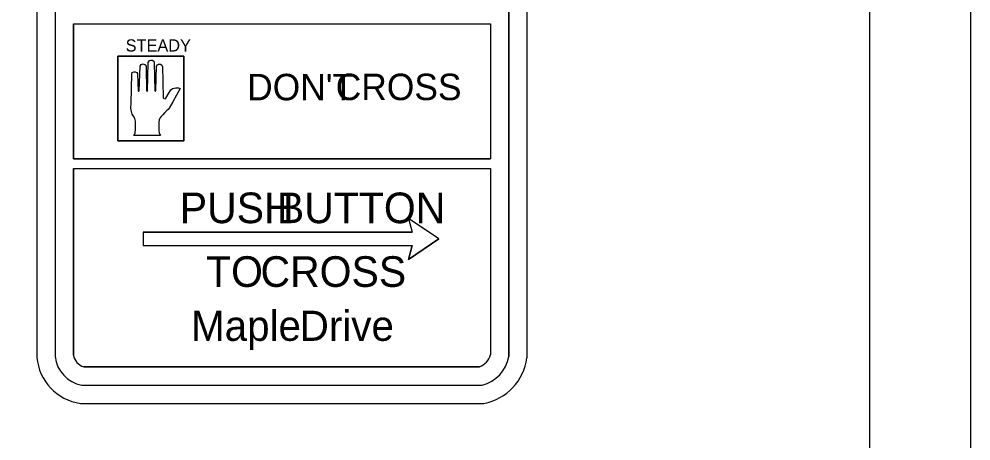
# Model space of a CAD drawing. Extents: x 1896459 to 1901611, y 1616229 to 1617416.
# Drawn here: x 1897924.9 to 1898159.1, y 1616865.6 to 1616969.5 of the extents above; entities that cross this region are included whole.
import ezdxf

# ---------------------------------------------------------------- set-up
doc = ezdxf.new("R2010")
doc.units = 0
for name, color, linetype in [('ROW_PR_Notes', 7, 'Continuous'), ('Sheets_General Details', 7, 'Continuous'), ('Signals_EX_Above Ground', 7, 'Continuous')]:
    doc.layers.add(name, color=color, linetype=linetype)

msp = doc.modelspace()

# ---------------------------------------------------------------- linework, layer by layer
at = {"layer": 'ROW_PR_Notes'}
for p, q in [((1897929.26, 1617065.93), (1897929.26, 1616886.19)), ((1897933.76, 1617065.54), (1897933.76, 1616886.41)), ((1897933.76, 1617065.54), (1897933.76, 1616886.41)), ((1898045.34, 1617065.54), (1898045.34, 1616886.41)), ((1898045.34, 1616886.41), (1898045.34, 1617065.54)), ((1898049.84, 1617065.89), (1898049.84, 1616886.08)), ((1897938.26, 1616968.32), (1898040.84, 1616968.32)), ((1897938.26, 1616968.32), (1897938.26, 1616935.04)), ((1897938.26, 1616968.32), (1898040.84, 1616968.32)), ((1897938.26, 1616935.04), (1897938.26, 1616968.32)), ((1898040.84, 1616968.32), (1898040.84, 1616935.04)), ((1898040.84, 1616968.32), (1898040.84, 1616935.04)), ((1897959.71, 1616940.81), (1897959.72, 1616940.82)), ((1897959.72, 1616940.82), (1897959.71, 1616940.81)), ((1897938.26, 1616935.04), (1898040.84, 1616935.04)), ((1898040.84, 1616935.04), (1897938.26, 1616935.04)), ((1897938.26, 1616932.71), (1898040.84, 1616932.71)), ((1897938.26, 1616932.71), (1897938.26, 1616886.7)), ((1897938.26, 1616886.7), (1897938.26, 1616932.71)), ((1897938.26, 1616932.71), (1898040.84, 1616932.71)), ((1898040.84, 1616932.71), (1898040.84, 1616886.85)), ((1898040.84, 1616932.71), (1898040.84, 1616886.85)), ((1898028.16, 1616915.34), (1898020.68, 1616920.42)), ((1898020.68, 1616920.42), (1898021.56, 1616916.98)), ((1898028.16, 1616915.34), (1898020.68, 1616920.42)), ((1898020.68, 1616920.42), (1898021.56, 1616916.98)), ((1897955.43, 1616916.98), (1897955.43, 1616913.71)), ((1897955.43, 1616916.98), (1898021.56, 1616916.98)), ((1898021.56, 1616916.98), (1897955.43, 1616916.98)), ((1897955.43, 1616916.98), (1897955.43, 1616913.71)), ((1898028.16, 1616915.34), (1898020.68, 1616910.27)), ((1898020.68, 1616910.27), (1898028.16, 1616915.34)), ((1897955.43, 1616913.71), (1898021.56, 1616913.71)), ((1897955.43, 1616913.71), (1898021.56, 1616913.71)), ((1898020.68, 1616910.27), (1898021.56, 1616913.71)), ((1898021.56, 1616913.71), (1898020.68, 1616910.27)), ((1897940.8, 1616883.88), (1898038.16, 1616883.88)), ((1898038.16, 1616883.88), (1897940.8, 1616883.88)), ((1897940.32, 1616879.38), (1898038.79, 1616879.38)), ((1897940.32, 1616879.38), (1898038.79, 1616879.38)), ((1897939.96, 1616874.88), (1898039.26, 1616874.88))]:
    msp.add_line(p, q, dxfattribs=at)
msp.add_lwpolyline([(1897949.15, 1616960.33), (1897965.4, 1616960.33), (1897965.4, 1616939.49), (1897949.15, 1616939.49)], close=True, dxfattribs=at)
for points in [[(1897949.15, 1616939.49), (1897965.4, 1616939.49), (1897965.4, 1616960.33), (1897949.15, 1616960.33), (1897949.15, 1616939.49)], [(1897959.71, 1616940.81), (1897953.09, 1616940.81), (1897953.42, 1616941.38), (1897953.55, 1616942.49), (1897953.56, 1616943.61), (1897953.54, 1616944.37), (1897953.37, 1616944.97), (1897953.06, 1616945.55), (1897952.75, 1616946.04), (1897952.48, 1616947.01), (1897952.42, 1616947.63), (1897952.43, 1616948.75), (1897952.59, 1616955.88), (1897952.75, 1616956.28), (1897953.13, 1616956.48), (1897953.48, 1616956.5), (1897953.82, 1616956.31), (1897953.99, 1616956.1), (1897954.01, 1616955.99), (1897954.22, 1616951.8), (1897954.29, 1616951.7), (1897954.35, 1616951.73), (1897954.47, 1616951.78), (1897954.65, 1616957.9), (1897954.91, 1616958.3), (1897955.42, 1616958.45), (1897955.94, 1616958.18), (1897956.12, 1616957.84), (1897956.14, 1616957.56), (1897956.26, 1616951.84), (1897956.38, 1616951.72), (1897956.52, 1616951.82), (1897956.68, 1616958.79), (1897956.98, 1616959.24), (1897957.28, 1616959.37), (1897957.66, 1616959.33), (1897958.01, 1616959.07), (1897958.16, 1616958.75), (1897958.3, 1616951.82), (1897958.42, 1616951.73), (1897958.55, 1616951.85), (1897958.69, 1616957.86), (1897958.91, 1616958.22), (1897959.21, 1616958.38), (1897959.68, 1616958.4), (1897960.03, 1616958.13), (1897960.18, 1616957.81), (1897960.25, 1616954.05), (1897960.37, 1616950.09), (1897960.54, 1616949.88), (1897960.79, 1616949.86), (1897960.98, 1616950.01), (1897962.24, 1616952.04), (1897962.67, 1616952.36), (1897963.43, 1616952.58), (1897964.09, 1616952.56), (1897964.54, 1616952.36), (1897962.71, 1616949.11), (1897961.81, 1616947.53), (1897961.56, 1616947.25), (1897961.25, 1616946.94), (1897960.76, 1616946.47), (1897960.25, 1616945.92), (1897959.83, 1616945.52), (1897959.51, 1616945.11), (1897959.32, 1616944.68), (1897959.27, 1616944.13), (1897959.28, 1616941.94), (1897959.36, 1616941.45), (1897959.54, 1616941.03), (1897959.72, 1616940.82)]]:
    msp.add_lwpolyline(points, dxfattribs=at)
for centre, radius, start, end in [((1897941.74, 1616887.27), 12.52, 184.9535, 261.8373), ((1897941.74, 1616887.27), 8.02, 186.1904, 259.7959), ((1897941.74, 1616887.27), 8.02, 186.1904, 259.7959), ((1897941.74, 1616887.27), 3.52, 189.3514, 254.5687), ((1897941.74, 1616887.27), 3.52, 189.3514, 254.5687), ((1898036.78, 1616887.82), 4.18, 289.3503, 346.4665), ((1898036.78, 1616887.82), 4.18, 289.3503, 346.4665), ((1898036.78, 1616887.82), 8.68, 283.3917, 350.622), ((1898036.78, 1616887.82), 8.68, 283.3917, 350.622), ((1898036.78, 1616887.82), 13.18, 280.8584, 352.393)]:
    msp.add_arc(centre, radius, start, end, dxfattribs=at)
at = {"layer": 'Sheets_General Details'}
msp.add_line((1898159.07, 1616316.47), (1898159.07, 1617416.47), dxfattribs=at)
for points in [[(1896459.07, 1616316.47), (1898159.07, 1616316.47), (1898159.07, 1617416.47), (1896459.07, 1617416.47)], [(1896559.07, 1617391.47), (1898134.07, 1617391.47), (1898134.07, 1616341.47), (1896559.07, 1616341.47)], [(1896559.07, 1617391.46), (1898134.07, 1617391.46), (1898134.07, 1616391.47), (1896559.07, 1616391.47)]]:
    msp.add_lwpolyline(points, close=True, dxfattribs=at)
at = {"layer": 'Signals_EX_Above Ground'}
msp.add_lwpolyline([(1897959.71, 1616940.81), (1897953.09, 1616940.81), (1897953.42, 1616941.38), (1897953.55, 1616942.49), (1897953.56, 1616943.61), (1897953.54, 1616944.37), (1897953.37, 1616944.97), (1897953.06, 1616945.55), (1897952.75, 1616946.04), (1897952.48, 1616947.01), (1897952.42, 1616947.63), (1897952.43, 1616948.75), (1897952.59, 1616955.88), (1897952.75, 1616956.28), (1897953.13, 1616956.48), (1897953.48, 1616956.5), (1897953.82, 1616956.31), (1897953.99, 1616956.1), (1897954.01, 1616955.99), (1897954.22, 1616951.8), (1897954.29, 1616951.7), (1897954.35, 1616951.73), (1897954.47, 1616951.78), (1897954.65, 1616957.9), (1897954.91, 1616958.3), (1897955.42, 1616958.45), (1897955.94, 1616958.18), (1897956.12, 1616957.84), (1897956.14, 1616957.56), (1897956.26, 1616951.84), (1897956.38, 1616951.72), (1897956.52, 1616951.82), (1897956.68, 1616958.79), (1897956.98, 1616959.24), (1897957.28, 1616959.37), (1897957.66, 1616959.33), (1897958.01, 1616959.07), (1897958.16, 1616958.75), (1897958.3, 1616951.82), (1897958.42, 1616951.73), (1897958.55, 1616951.85), (1897958.69, 1616957.86), (1897958.91, 1616958.22), (1897959.21, 1616958.38), (1897959.68, 1616958.4), (1897960.03, 1616958.13), (1897960.18, 1616957.81), (1897960.25, 1616954.05), (1897960.37, 1616950.09), (1897960.54, 1616949.88), (1897960.79, 1616949.86), (1897960.98, 1616950.01), (1897962.24, 1616952.04), (1897962.67, 1616952.36), (1897963.43, 1616952.58), (1897964.09, 1616952.56), (1897964.54, 1616952.36), (1897962.71, 1616949.11), (1897961.81, 1616947.53), (1897961.56, 1616947.25), (1897961.25, 1616946.94), (1897960.76, 1616946.47), (1897960.25, 1616945.92), (1897959.83, 1616945.52), (1897959.51, 1616945.11), (1897959.32, 1616944.68), (1897959.27, 1616944.13), (1897959.28, 1616941.94), (1897959.36, 1616941.45), (1897959.54, 1616941.03), (1897959.72, 1616940.82)], dxfattribs=at)

# ---------------------------------------------------------------- texts
at = {"layer": 'ROW_PR_Notes'}
for s, height, p in [('STEADY', 3.001, (1897951.11, 1616961.48)), ("DON'T", 6.509, (1897981, 1616949.48)), ('CROSS', 6.509, (1898002.79, 1616949.52)), ('PUSH', 7.537, (1897964.43, 1616919.23)), ('BUTTON', 7.537, (1897988.32, 1616919.23)), ('TO', 7.537, (1897970.89, 1616903.55)), ('CROSS', 7.537, (1897984.28, 1616903.55)), ('Maple', 7.425, (1897967.2, 1616890.26)), ('Drive', 7.425, (1897993.94, 1616890.26))]:
    msp.add_text(s, height=height, dxfattribs=at).set_placement(p)

doc.saveas('drawing.dxf')
